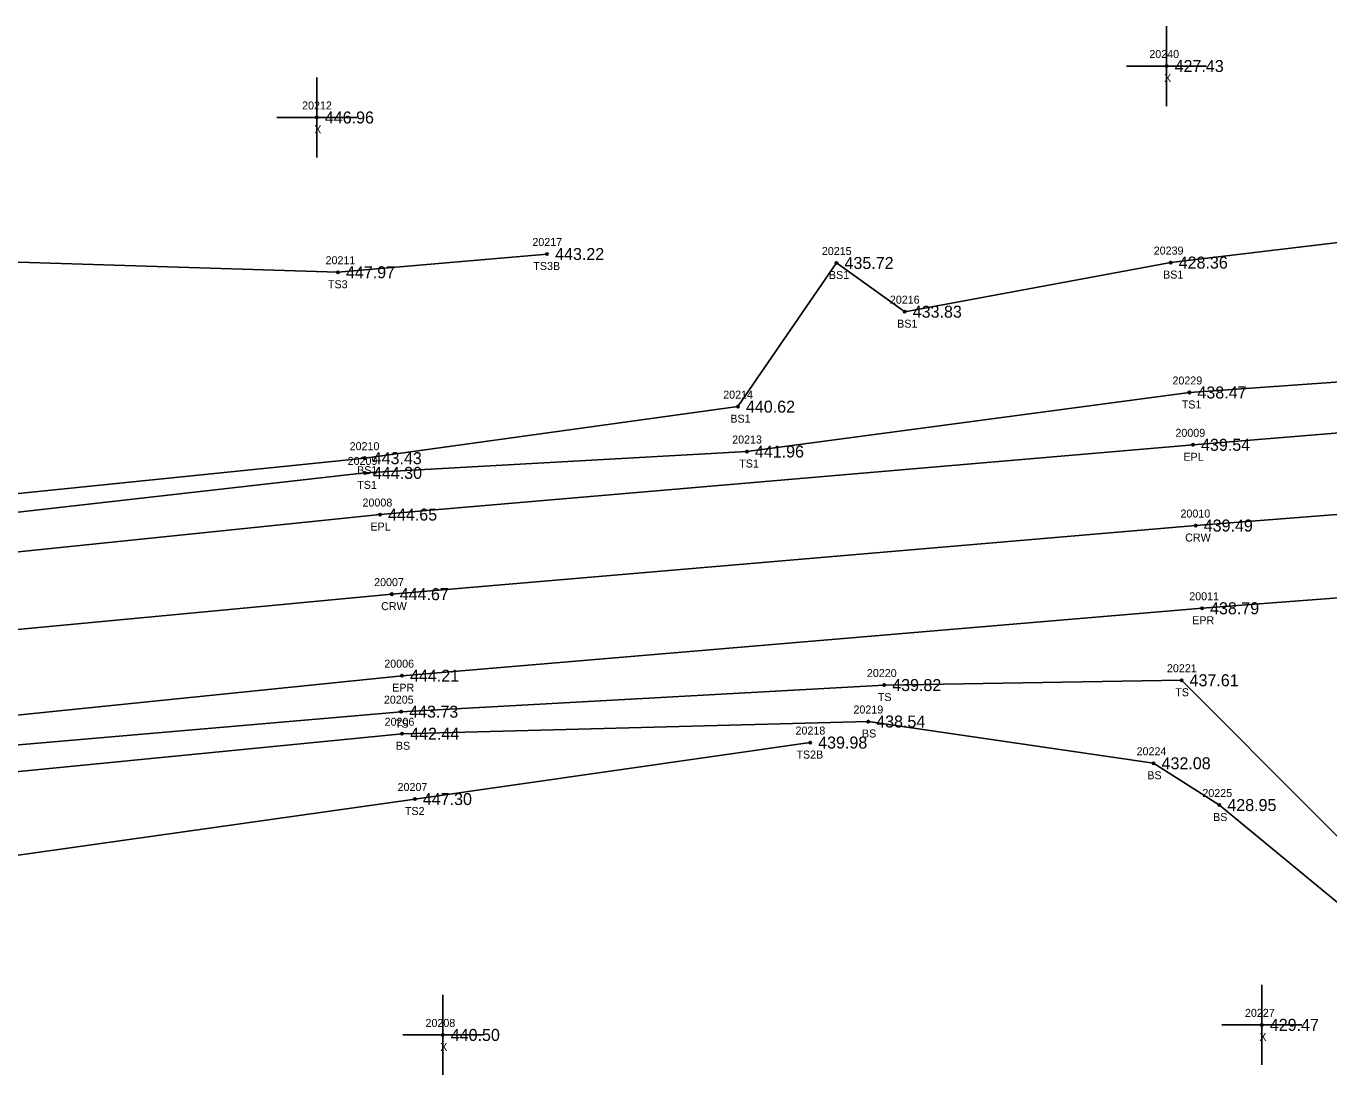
# Model space of a CAD drawing. Extents: x 1613184 to 1614731, y 770859 to 771868.
# Drawn here: x 1613346.8 to 1613509.6, y 771278.4 to 771409.5 of the extents above; entities that cross this region are included whole.
import ezdxf

# ---------------------------------------------------------------- set-up
doc = ezdxf.new("R2010")
doc.units = 0
for name, color, linetype in [('RD_DTM_BkLn1', 7, 'Continuous'), ('RD_DTM_BkLn2', 7, 'Continuous'), ('RD_DTM_BkLn_txCode', 7, 'Continuous'), ('RD_EX_Misc', 7, 'Continuous'), ('RD_EX_Misc_txCode', 7, 'Continuous'), ('RD_EX_Road', 7, 'Continuous'), ('RD_EX_Road_txCode', 7, 'Continuous'), ('RD_EX_TX_Misc_ELEV', 7, 'Continuous'), ('RD_EX_TX_Road_ELEV', 7, 'Continuous'), ('RD_HC_Survey_ELEV', 7, 'Continuous'), ('RD_HC_Survey_txCode', 7, 'Continuous'), ('RD_SMD_Locator', 7, 'Continuous')]:
    doc.layers.add(name, color=color, linetype=linetype)

msp = doc.modelspace()

# ---------------------------------------------------------------- linework, layer by layer
at = {"layer": 'RD_DTM_BkLn1'}
msp.add_lwpolyline([(1613193.64, 771319.41), (1613293.11, 771329.14), (1613392.46, 771338.5), (1613492.95, 771347.08), (1613542.61, 771350.97), (1613592.52, 771354.09), (1613642.63, 771355.86), (1613692.27, 771356.69), (1613742.08, 771356.79), (1613792.13, 771355.6), (1613841.94, 771351.86), (1613890.87, 771346.48)], dxfattribs=at)
at = {"layer": 'RD_DTM_BkLn2'}
for points in [[(1613191.9, 771337.48), (1613291.44, 771345.53), (1613389.08, 771355.5), (1613435.73, 771361.94), (1613448.05, 771379.9), (1613456.58, 771373.81), (1613489.82, 771379.95), (1613539.65, 771385.9), (1613590.16, 771390.66), (1613642.18, 771393.2), (1613691.23, 771395.53), (1613743.12, 771392.35), (1613794.87, 771390.82), (1613846.37, 771384.69), (1613895.3, 771384.28), (1613914.84, 771377.38)], [(1613189.64, 771362.94), (1613287.23, 771381.82), (1613385.74, 771378.74), (1613411.88, 771381.02)], [(1613192.28, 771333.37), (1613291.74, 771342.64), (1613389.11, 771353.66), (1613436.85, 771356.33), (1613492.16, 771363.71), (1613540.47, 771367.11), (1613591.24, 771372.7), (1613642.11, 771373.16), (1613691.12, 771373.65), (1613744.36, 771374.73), (1613793.64, 771374.02), (1613845.39, 771367.84), (1613892.43, 771366.82), (1613891.67, 771360.8)], [(1613195.19, 771306.21), (1613295.11, 771315.27), (1613393.64, 771323.81), (1613454.01, 771327.14), (1613491.18, 771327.74), (1613525.58, 771293.23)], [(1613195.67, 771302.8), (1613295.8, 771311.41), (1613393.76, 771321.05), (1613452.01, 771322.58), (1613487.68, 771317.36), (1613495.9, 771312.14), (1613522.8, 771289.94)], [(1613196.47, 771290.95), (1613297.34, 771299.06), (1613395.35, 771312.89), (1613444.76, 771319.95)]]:
    msp.add_lwpolyline(points, dxfattribs=at)
at = {"layer": 'RD_EX_Misc'}
for p, q in [((1613489.31, 771399.52), (1613489.31, 771409.52)), ((1613484.31, 771404.52), (1613494.31, 771404.52)), ((1613383.1, 771393.09), (1613383.1, 771403.09)), ((1613378.1, 771398.09), (1613388.1, 771398.09)), ((1613398.84, 771278.4), (1613398.84, 771288.4)), ((1613501.21, 771279.66), (1613501.21, 771289.66)), ((1613393.84, 771283.4), (1613403.84, 771283.4)), ((1613496.21, 771284.66), (1613506.21, 771284.66))]:
    msp.add_line(p, q, dxfattribs=at)
at = {"layer": 'RD_EX_Road'}
for points in [[(1613192.48, 771329.15), (1613292.05, 771338.23), (1613391, 771348.45), (1613492.61, 771357.17), (1613541.86, 771361.21), (1613591.56, 771364.71), (1613642.92, 771366.4), (1613692.81, 771367.35), (1613742.66, 771367.02), (1613792.19, 771365.04), (1613843.32, 771361.63), (1613887.78, 771357.57), (1613892.3, 771358.63)], [(1613194.6, 771309.27), (1613294.55, 771318.15), (1613393.75, 771328.31), (1613493.74, 771336.74), (1613544.27, 771340.57), (1613593.48, 771343.76), (1613642.77, 771345.54), (1613692.58, 771346.11), (1613741.71, 771345.82), (1613791.79, 771344.79), (1613840.79, 771341.46), (1613889.25, 771335.84)]]:
    msp.add_lwpolyline(points, dxfattribs=at)
at = {"layer": 'RD_SMD_Locator'}
for centre in [(1613489.31, 771404.52), (1613383.1, 771398.09), (1613411.88, 771381.02), (1613448.05, 771379.9), (1613489.82, 771379.95), (1613385.74, 771378.74), (1613456.58, 771373.81), (1613492.16, 771363.71), (1613435.73, 771361.94), (1613492.61, 771357.17), (1613389.08, 771355.5), (1613436.85, 771356.33), (1613389.11, 771353.66), (1613391, 771348.45), (1613492.95, 771347.08), (1613392.46, 771338.5), (1613493.74, 771336.74), (1613393.75, 771328.31), (1613454.01, 771327.14), (1613491.18, 771327.74), (1613393.64, 771323.81), (1613452.01, 771322.58), (1613393.76, 771321.05), (1613444.76, 771319.95), (1613487.68, 771317.36), (1613395.35, 771312.89), (1613495.9, 771312.14), (1613398.84, 771283.4), (1613501.21, 771284.66)]:
    msp.add_circle(centre, 0.15, dxfattribs=at)

# ---------------------------------------------------------------- texts
at = {"layer": 'RD_DTM_BkLn_txCode'}
for s, p in [('20217', (1613410.04, 771382.02)), ('20215', (1613446.22, 771380.9)), ('20239', (1613487.7, 771380.95)), ('20211', (1613384.19, 771379.74)), ('TS3B', (1613410.16, 771379.02)), ('TS3', (1613384.49, 771376.74)), ('BS1', (1613447.1, 771377.9)), ('BS1', (1613488.87, 771377.95)), ('20216', (1613454.72, 771374.81)), ('BS1', (1613455.63, 771371.81)), ('20229', (1613490.04, 771364.71)), ('20214', (1613433.89, 771362.94)), ('TS1', (1613491.2, 771361.71)), ('BS1', (1613434.78, 771359.94)), ('20213', (1613435.01, 771357.33)), ('20210', (1613387.2, 771356.5)), ('20209', (1613386.95, 771354.66)), ('TS1', (1613435.89, 771354.33)), ('BS1', (1613388.13, 771353.5)), ('TS1', (1613388.15, 771351.66)), ('20220', (1613451.85, 771328.14)), ('20221', (1613489.35, 771328.74)), ('20205', (1613391.48, 771324.81)), ('TS', (1613453.21, 771325.14)), ('TS', (1613490.39, 771325.74)), ('20219', (1613450.17, 771323.58)), ('20206', (1613391.57, 771322.05)), ('TS', (1613392.85, 771321.81)), ('20218', (1613442.93, 771320.95)), ('BS', (1613451.23, 771320.58)), ('BS', (1613392.98, 771319.05)), ('20224', (1613485.56, 771318.36)), ('TS2B', (1613443.04, 771317.95)), ('BS', (1613486.9, 771315.36)), ('20207', (1613393.19, 771313.89)), ('20225', (1613493.78, 771313.14)), ('TS2', (1613394.11, 771310.89)), ('BS', (1613495.12, 771310.14))]:
    msp.add_text(s, height=1, dxfattribs=at).set_placement(p)
at = {"layer": 'RD_EX_Misc_txCode'}
for s, p in [('20240', (1613487.15, 771405.52)), ('X', (1613488.99, 771402.52)), ('20212', (1613381.26, 771399.09)), ('X', (1613382.78, 771396.09)), ('20227', (1613499.1, 771285.66)), ('20208', (1613396.68, 771284.4)), ('X', (1613500.9, 771282.66)), ('X', (1613398.52, 771281.4))]:
    msp.add_text(s, height=1, dxfattribs=at).set_placement(p)
at = {"layer": 'RD_EX_Road_txCode'}
for s, p in [('20009', (1613490.41, 771358.17)), ('EPL', (1613491.41, 771355.17)), ('20008', (1613388.81, 771349.45)), ('EPL', (1613389.8, 771346.45)), ('20011', (1613492.14, 771337.74)), ('EPR', (1613492.51, 771334.74)), ('20006', (1613391.53, 771329.31)), ('EPR', (1613392.52, 771326.31))]:
    msp.add_text(s, height=1, dxfattribs=at).set_placement(p)
at = {"layer": 'RD_EX_TX_Misc_ELEV'}
for s, p in [('427.43', (1613490.31, 771403.77)), ('446.96', (1613384.1, 771397.34)), ('443.22', (1613412.88, 771380.27)), ('447.97', (1613386.74, 771377.99)), ('435.72', (1613449.05, 771379.15)), ('428.36', (1613490.82, 771379.2)), ('433.83', (1613457.58, 771373.06)), ('438.47', (1613493.16, 771362.96)), ('440.62', (1613436.73, 771361.19)), ('441.96', (1613437.85, 771355.58)), ('443.43', (1613390.08, 771354.75)), ('444.30', (1613390.11, 771352.91)), ('439.82', (1613455.01, 771326.39)), ('437.61', (1613492.18, 771326.99)), ('443.73', (1613394.64, 771323.06)), ('438.54', (1613453.01, 771321.83)), ('442.44', (1613394.76, 771320.3)), ('439.98', (1613445.76, 771319.2)), ('432.08', (1613488.68, 771316.61)), ('447.30', (1613396.35, 771312.14)), ('428.95', (1613496.9, 771311.39)), ('429.47', (1613502.21, 771283.91)), ('440.50', (1613399.84, 771282.65))]:
    msp.add_text(s, height=1.5, dxfattribs=at).set_placement(p)
at = {"layer": 'RD_EX_TX_Road_ELEV'}
for s, p in [('439.54', (1613493.61, 771356.42)), ('444.65', (1613392, 771347.7)), ('438.79', (1613494.74, 771335.99)), ('444.21', (1613394.75, 771327.56))]:
    msp.add_text(s, height=1.5, dxfattribs=at).set_placement(p)
at = {"layer": 'RD_HC_Survey_ELEV'}
for s, p in [('439.49', (1613493.95, 771346.33)), ('444.67', (1613393.46, 771337.75))]:
    msp.add_text(s, height=1.5, dxfattribs=at).set_placement(p)
at = {"layer": 'RD_HC_Survey_txCode'}
for s, p in [('20010', (1613491.04, 771348.08)), ('CRW', (1613491.63, 771345.08)), ('20007', (1613390.26, 771339.5)), ('CRW', (1613391.14, 771336.5))]:
    msp.add_text(s, height=1, dxfattribs=at).set_placement(p)

doc.saveas('drawing.dxf')
